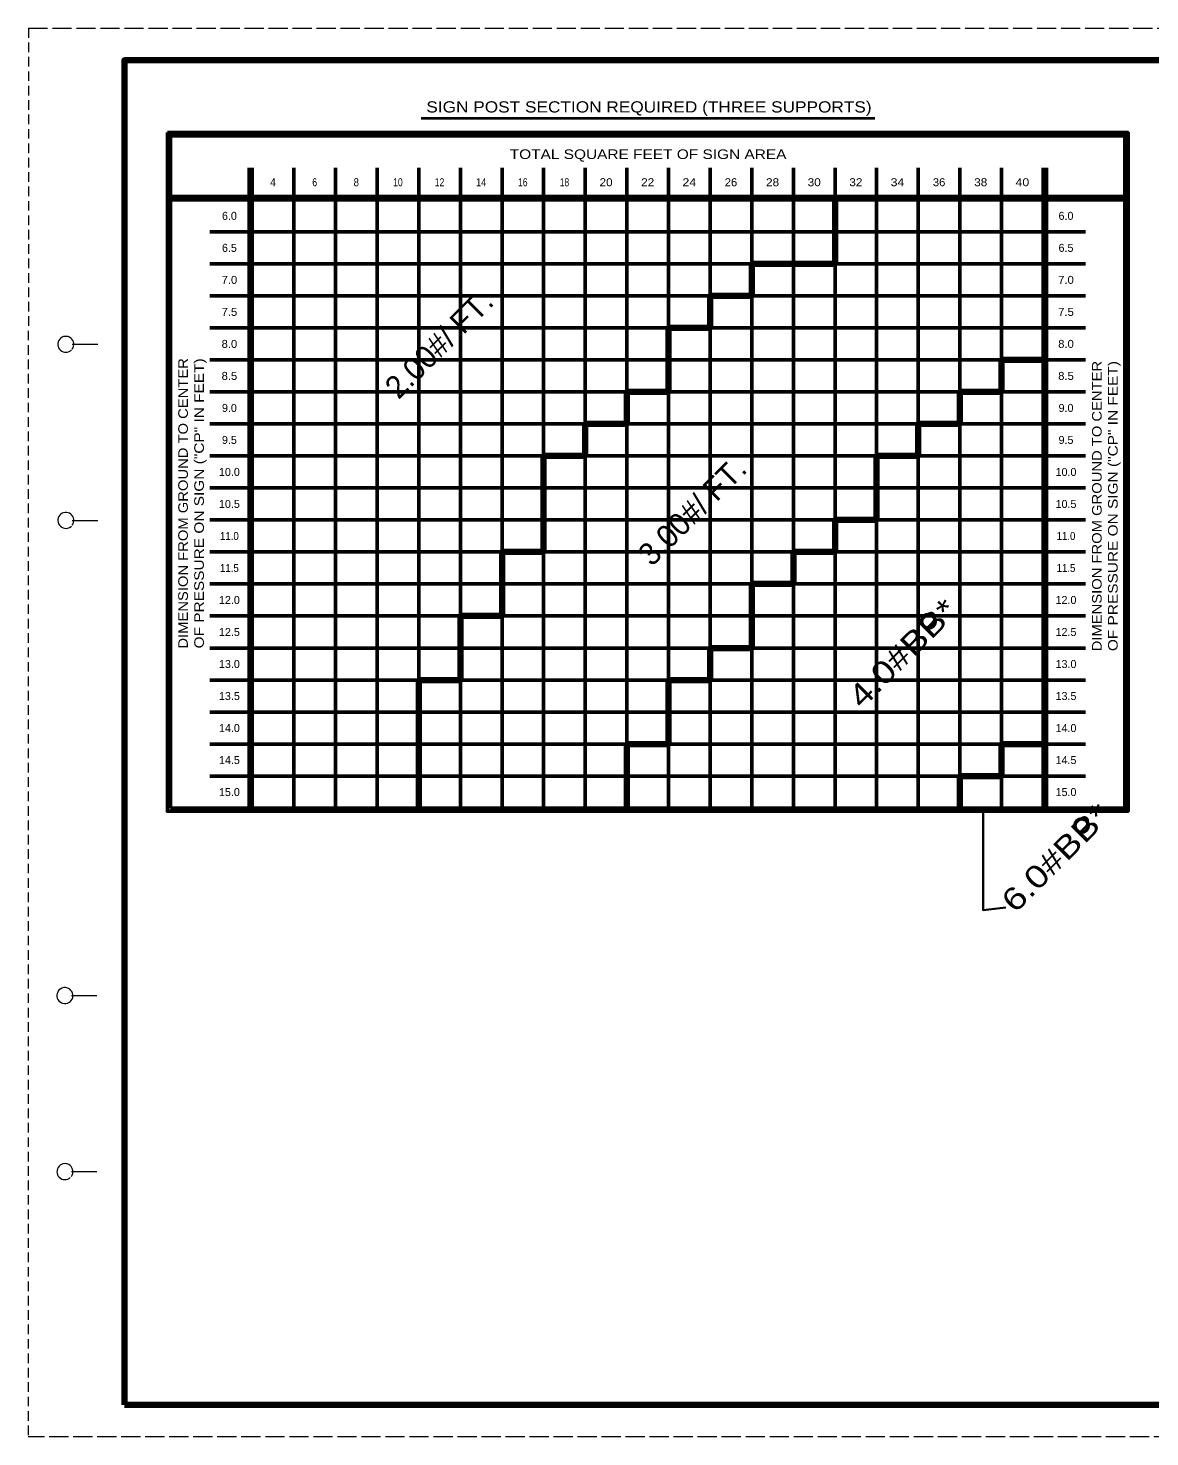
# Model space of a CAD drawing. Extents: x -2 to 679, y 0 to 440.
# Drawn here: x -1.5 to 348.7, y -0.3 to 439.8 of the extents above; entities that cross this region are included whole.
import ezdxf
from ezdxf.enums import TextEntityAlignment as Align

# ---------------------------------------------------------------- set-up
doc = ezdxf.new("R2010")
doc.units = 0
doc.linetypes.add('LONG_DASHED', pattern=[7.5, 6, -1.5])
doc.linetypes.add('MEDIUM_DASHED', pattern=[4.5, 3, -1.5])
doc.layers.add('1', color=7, linetype='Continuous', lineweight=53)
doc.layers.add('61', color=7, linetype='Continuous', lineweight=35)

msp = doc.modelspace()

# ---------------------------------------------------------------- linework, layer by layer
at = {"layer": '1', "linetype": 'MEDIUM_DASHED', "lineweight": 13}
msp.add_line((-1.478, 439.764), (-1.538, -0.276), dxfattribs=at)
at = {"layer": '1', "lineweight": 40}
msp.add_line((121.189, 411.615), (262.807, 411.615), dxfattribs=at)
at = {"layer": '1'}
for p, q in [((67.426, 196.137), (67.426, 396.137)), ((68.426, 196.137), (68.426, 396.137)), ((94.426, 196.137), (94.426, 396.137)), ((107.426, 196.137), (107.426, 396.137)), ((120.426, 236.137), (120.426, 396.137)), ((133.426, 256.137), (133.426, 396.137)), ((146.426, 276.137), (146.426, 396.137)), ((159.426, 306.137), (159.426, 396.137)), ((172.426, 316.137), (172.426, 396.137)), ((185.426, 326.137), (185.426, 396.137)), ((198.426, 346.137), (198.426, 396.137)), ((211.426, 356.137), (211.426, 396.137)), ((224.426, 366.137), (224.426, 396.137)), ((237.426, 276.137), (237.426, 396.137)), ((250.426, 386.137), (250.426, 396.137)), ((263.426, 306.137), (263.426, 396.137)), ((276.426, 316.137), (276.426, 396.137)), ((289.426, 326.137), (289.426, 396.137)), ((302.426, 336.137), (302.426, 396.137)), ((315.426, 396.137), (315.426, 196.137)), ((316.426, 396.137), (316.426, 196.137)), ((42.926, 387.137), (340.926, 387.137)), ((42.926, 386.137), (340.926, 386.137)), ((55.176, 376.137), (67.426, 376.137)), ((68.426, 376.137), (316.426, 376.137)), ((316.426, 376.137), (328.676, 376.137)), ((55.176, 366.137), (224.426, 366.137)), ((250.426, 366.137), (328.676, 366.137)), ((250.426, 286.137), (250.426, 366.137)), ((55.176, 356.137), (211.426, 356.137)), ((224.426, 356.137), (328.676, 356.137)), ((224.426, 266.137), (224.426, 356.137)), ((55.176, 346.137), (198.426, 346.137)), ((211.426, 346.137), (328.676, 346.137)), ((211.426, 246.137), (211.426, 346.137)), ((55.176, 336.137), (302.426, 336.137)), ((315.426, 336.137), (328.676, 336.137)), ((55.176, 326.137), (185.426, 326.137)), ((198.426, 236.137), (198.426, 326.137)), ((198.426, 326.137), (289.426, 326.137)), ((302.426, 326.137), (328.676, 326.137)), ((302.426, 216.137), (302.426, 326.137)), ((55.176, 316.137), (172.426, 316.137)), ((185.426, 216.137), (185.426, 316.137)), ((185.426, 316.137), (276.426, 316.137)), ((289.426, 316.137), (328.676, 316.137)), ((289.426, 206.137), (289.426, 316.137)), ((55.176, 306.137), (159.426, 306.137)), ((172.426, 196.137), (172.426, 306.137)), ((172.426, 306.137), (263.426, 306.137)), ((276.426, 306.137), (328.676, 306.137)), ((276.426, 196.137), (276.426, 306.137)), ((55.176, 296.137), (328.676, 296.137)), ((55.176, 286.137), (250.426, 286.137)), ((263.426, 286.137), (328.676, 286.137)), ((263.426, 196.137), (263.426, 286.137)), ((55.176, 276.137), (146.426, 276.137)), ((159.426, 196.137), (159.426, 276.137)), ((159.426, 276.137), (237.426, 276.137)), ((250.426, 276.137), (328.676, 276.137)), ((250.426, 196.137), (250.426, 276.137)), ((55.176, 266.137), (224.426, 266.137)), ((237.426, 266.137), (328.676, 266.137)), ((237.426, 196.137), (237.426, 266.137)), ((55.176, 256.137), (133.426, 256.137)), ((146.426, 256.137), (328.676, 256.137)), ((146.426, 196.137), (146.426, 256.137)), ((55.176, 246.137), (211.426, 246.137)), ((224.426, 246.137), (328.676, 246.137)), ((224.426, 196.137), (224.426, 246.137)), ((55.176, 236.137), (120.426, 236.137)), ((133.426, 196.137), (133.426, 236.137)), ((133.426, 236.137), (198.426, 236.137)), ((211.426, 236.137), (328.676, 236.137)), ((211.426, 196.137), (211.426, 236.137)), ((55.176, 226.137), (328.676, 226.137)), ((55.176, 216.137), (185.426, 216.137)), ((198.426, 196.137), (198.426, 216.137)), ((198.426, 216.137), (302.426, 216.137)), ((315.426, 216.137), (328.676, 216.137)), ((55.176, 206.137), (289.426, 206.137)), ((302.426, 206.137), (328.676, 206.137)), ((302.426, 196.137), (302.426, 206.137))]:
    msp.add_line(p, q, dxfattribs=at)
at = {"layer": '1', "lineweight": 200}
for p, q in [((250.426, 366.137), (250.426, 386.137)), ((224.426, 356.137), (224.426, 366.137)), ((224.426, 366.137), (250.426, 366.137)), ((211.426, 346.137), (211.426, 356.137)), ((211.426, 356.137), (224.426, 356.137)), ((198.426, 326.137), (198.426, 346.137)), ((198.426, 346.137), (211.426, 346.137)), ((302.426, 326.137), (302.426, 336.137)), ((302.426, 336.137), (315.426, 336.137)), ((185.426, 316.137), (185.426, 326.137)), ((185.426, 326.137), (198.426, 326.137)), ((289.426, 316.137), (289.426, 326.137)), ((289.426, 326.137), (302.426, 326.137)), ((172.426, 306.137), (172.426, 316.137)), ((172.426, 316.137), (185.426, 316.137)), ((276.426, 306.137), (276.426, 316.137)), ((276.426, 316.137), (289.426, 316.137)), ((159.426, 276.137), (159.426, 306.137)), ((159.426, 306.137), (172.426, 306.137)), ((263.426, 286.137), (263.426, 306.137)), ((263.426, 306.137), (276.426, 306.137)), ((250.426, 276.137), (250.426, 286.137)), ((250.426, 286.137), (263.426, 286.137)), ((146.426, 256.137), (146.426, 276.137)), ((146.426, 276.137), (159.426, 276.137)), ((237.426, 266.137), (237.426, 276.137)), ((237.426, 276.137), (250.426, 276.137)), ((224.426, 246.137), (224.426, 266.137)), ((224.426, 266.137), (237.426, 266.137)), ((133.426, 236.137), (133.426, 256.137)), ((133.426, 256.137), (146.426, 256.137)), ((211.426, 236.137), (211.426, 246.137)), ((211.426, 246.137), (224.426, 246.137)), ((120.426, 196.137), (120.426, 236.137)), ((120.426, 236.137), (133.426, 236.137)), ((198.426, 216.137), (198.426, 236.137)), ((198.426, 236.137), (211.426, 236.137)), ((185.426, 196.137), (185.426, 216.137)), ((185.426, 216.137), (198.426, 216.137)), ((302.426, 206.137), (302.426, 216.137)), ((302.426, 216.137), (315.426, 216.137)), ((289.426, 196.137), (289.426, 206.137)), ((289.426, 206.137), (302.426, 206.137))]:
    msp.add_line(p, q, dxfattribs=at)
at = {"layer": '1'}
for points in [[(41.926, 407.137), (341.926, 407.137), (341.926, 195.137), (41.926, 195.137)], [(42.926, 196.137), (42.926, 406.137), (340.926, 406.137), (340.926, 196.137)]]:
    msp.add_lwpolyline(points, close=True, dxfattribs=at)
msp.add_lwpolyline([(81.426, 196.137), (81.426, 386.137), (81.426, 396.137)], dxfattribs=at)
at = {"layer": '1', "lineweight": 35}
msp.add_lwpolyline([(296.667, 196.137), (296.667, 164.25), (303.75, 165.083)], dxfattribs=at)
at = {"layer": '1'}
for centre, radius in [((279.583, 254.5), 2.125), ((327.417, 190.667), 2.103)]:
    msp.add_circle(centre, radius, dxfattribs=at)
at = {"layer": '61', "linetype": 'LONG_DASHED', "lineweight": 13}
for p, q in [((-1.478, 439.764), (678.541, 439.764)), ((678.521, -0.256), (-1.538, -0.276))]:
    msp.add_line(p, q, dxfattribs=at)
at = {"layer": '61', "lineweight": 13}
for p, q in [((12.242, 341.004), (20.221, 341.024)), ((12.221, 286.004), (20.221, 286.004)), ((11.941, 137.584), (19.941, 137.584)), ((11.961, 82.564), (19.941, 82.564))]:
    msp.add_line(p, q, dxfattribs=at)
at = {"layer": '61', "lineweight": 158}
msp.add_line((667.582, 9.724), (28.521, 9.744), dxfattribs=at)
msp.add_lwpolyline([(667.562, 429.764), (28.521, 429.764), (28.521, 9.744)], dxfattribs=at)
at = {"layer": '61', "lineweight": 13}
for centre, start, end in [((10.219, 341.005), 323.13009, 316.23216), ((10.219, 286.005), 323.13009, 315.37577), ((9.939, 137.565), 322.67175, 321.71615), ((9.939, 82.565), 323.13009, 312.31439)]:
    msp.add_arc(centre, 2.5, start, end, dxfattribs=at)

# ---------------------------------------------------------------- texts
at = {"layer": '1'}
for s, height, width, p in [('SIGN POST SECTION REQUIRED (THREE SUPPORTS)', 3.5, 1.15, (192.323, 413.422)), ('TOTAL SQUARE FEET OF SIGN AREA', 3, 1.2, (192.049, 398.894)), ('4', 2.5, 0.95, (74.926, 390.387)), ('6', 2.5, 0.8, (87.926, 390.387)), ('8', 2.5, 0.9, (100.926, 390.387)), ('10', 2.5, 0.8, (113.926, 390.387)), ('12', 2.5, 0.8, (126.926, 390.387)), ('14', 2.5, 0.85, (139.926, 390.387)), ('16', 2.5, 0.8, (152.926, 390.387)), ('18', 2.5, 0.8, (165.926, 390.387)), ('20', 2.5, 1.1, (178.926, 390.387)), ('22', 2.5, 1.1, (191.926, 390.387)), ('24', 2.5, 1.15, (204.926, 390.387)), ('26', 2.5, 1.05, (217.926, 390.387)), ('28', 2.5, 1.1, (230.926, 390.387)), ('30', 2.5, 1.1, (243.926, 390.387)), ('32', 2.5, 1.1, (256.926, 390.387)), ('34', 2.5, 1.15, (269.926, 390.387)), ('36', 2.5, 1.05, (282.926, 390.387)), ('38', 2.5, 1.1, (295.926, 390.387)), ('40', 2.5, 1.15, (308.926, 390.387)), ('7.0', 2.5, 1.05, (61.301, 359.887)), ('7.0', 2.5, 1.05, (322.551, 359.887)), ('7.5', 2.5, 1.05, (61.301, 349.887)), ('7.5', 2.5, 1.05, (322.551, 349.887)), ('8.0', 2.5, 1.05, (61.301, 339.887)), ('8.0', 2.5, 1.05, (322.551, 339.887)), ('8.5', 2.5, 1.05, (61.301, 329.887)), ('8.5', 2.5, 1.05, (322.551, 329.887)), ('11.0', 2.5, 0.9, (61.301, 279.887)), ('11.0', 2.5, 0.9, (322.551, 279.887)), ('11.5', 2.5, 0.9, (61.301, 269.887)), ('11.5', 2.5, 0.9, (322.551, 269.887))]:
    msp.add_text(s, height=height, dxfattribs=dict(at, width=width)).set_placement(p, align=Align.CENTER)
for s, p in [('6.0', (61.301, 379.887)), ('6.0', (322.551, 379.887)), ('6.5', (61.301, 369.887)), ('6.5', (322.551, 369.887)), ('9.0', (61.301, 319.887)), ('9.0', (322.551, 319.887)), ('9.5', (61.301, 309.887)), ('9.5', (322.551, 309.887)), ('10.0', (61.301, 299.887)), ('10.0', (322.551, 299.887)), ('10.5', (61.301, 289.887)), ('10.5', (322.551, 289.887)), ('12.0', (61.301, 259.887)), ('12.0', (322.551, 259.887)), ('12.5', (61.301, 249.887)), ('12.5', (322.551, 249.887)), ('13.0', (61.301, 239.887)), ('13.0', (322.551, 239.887)), ('13.5', (61.301, 229.887)), ('13.5', (322.551, 229.887)), ('14.0', (61.301, 219.887)), ('14.0', (322.551, 219.887)), ('14.5', (61.301, 209.887)), ('14.5', (322.551, 209.887)), ('15.0', (61.301, 199.887)), ('15.0', (322.551, 199.887))]:
    msp.add_text(s, height=2.5, dxfattribs=at).set_placement(p, align=Align.CENTER)
for s, p in [('2.00#/ FT.', (129.217, 338.655)), ('3.00#/ FT.', (208.31, 286.411))]:
    msp.add_text(s, height=7, rotation=45, dxfattribs=at).set_placement(p, align=Align.CENTER)
for s, height, rotation, width, p in [('DIMENSION FROM GROUND TO CENTER', 3, 90, 1.15, (48.323, 291.317)), ('OF PRESSURE ON SIGN ("CP" IN FEET)', 3, 90, 1.2, (53.323, 291.317)), ('DIMENSION FROM GROUND TO CENTER', 3, 90, 1.15, (333.685, 290.472)), ('OF PRESSURE ON SIGN ("CP" IN FEET)', 3, 90, 1.2, (338.685, 290.472)), ('4.0#BB*', 7, 45, 1.25, (274.033, 242.083)), ('6.0#BB*', 7, 45, 1.25, (321.866, 178.25))]:
    msp.add_text(s, height=height, rotation=rotation, dxfattribs=dict(at, width=width)).set_placement(p, align=Align.CENTER)

doc.saveas('drawing.dxf')
